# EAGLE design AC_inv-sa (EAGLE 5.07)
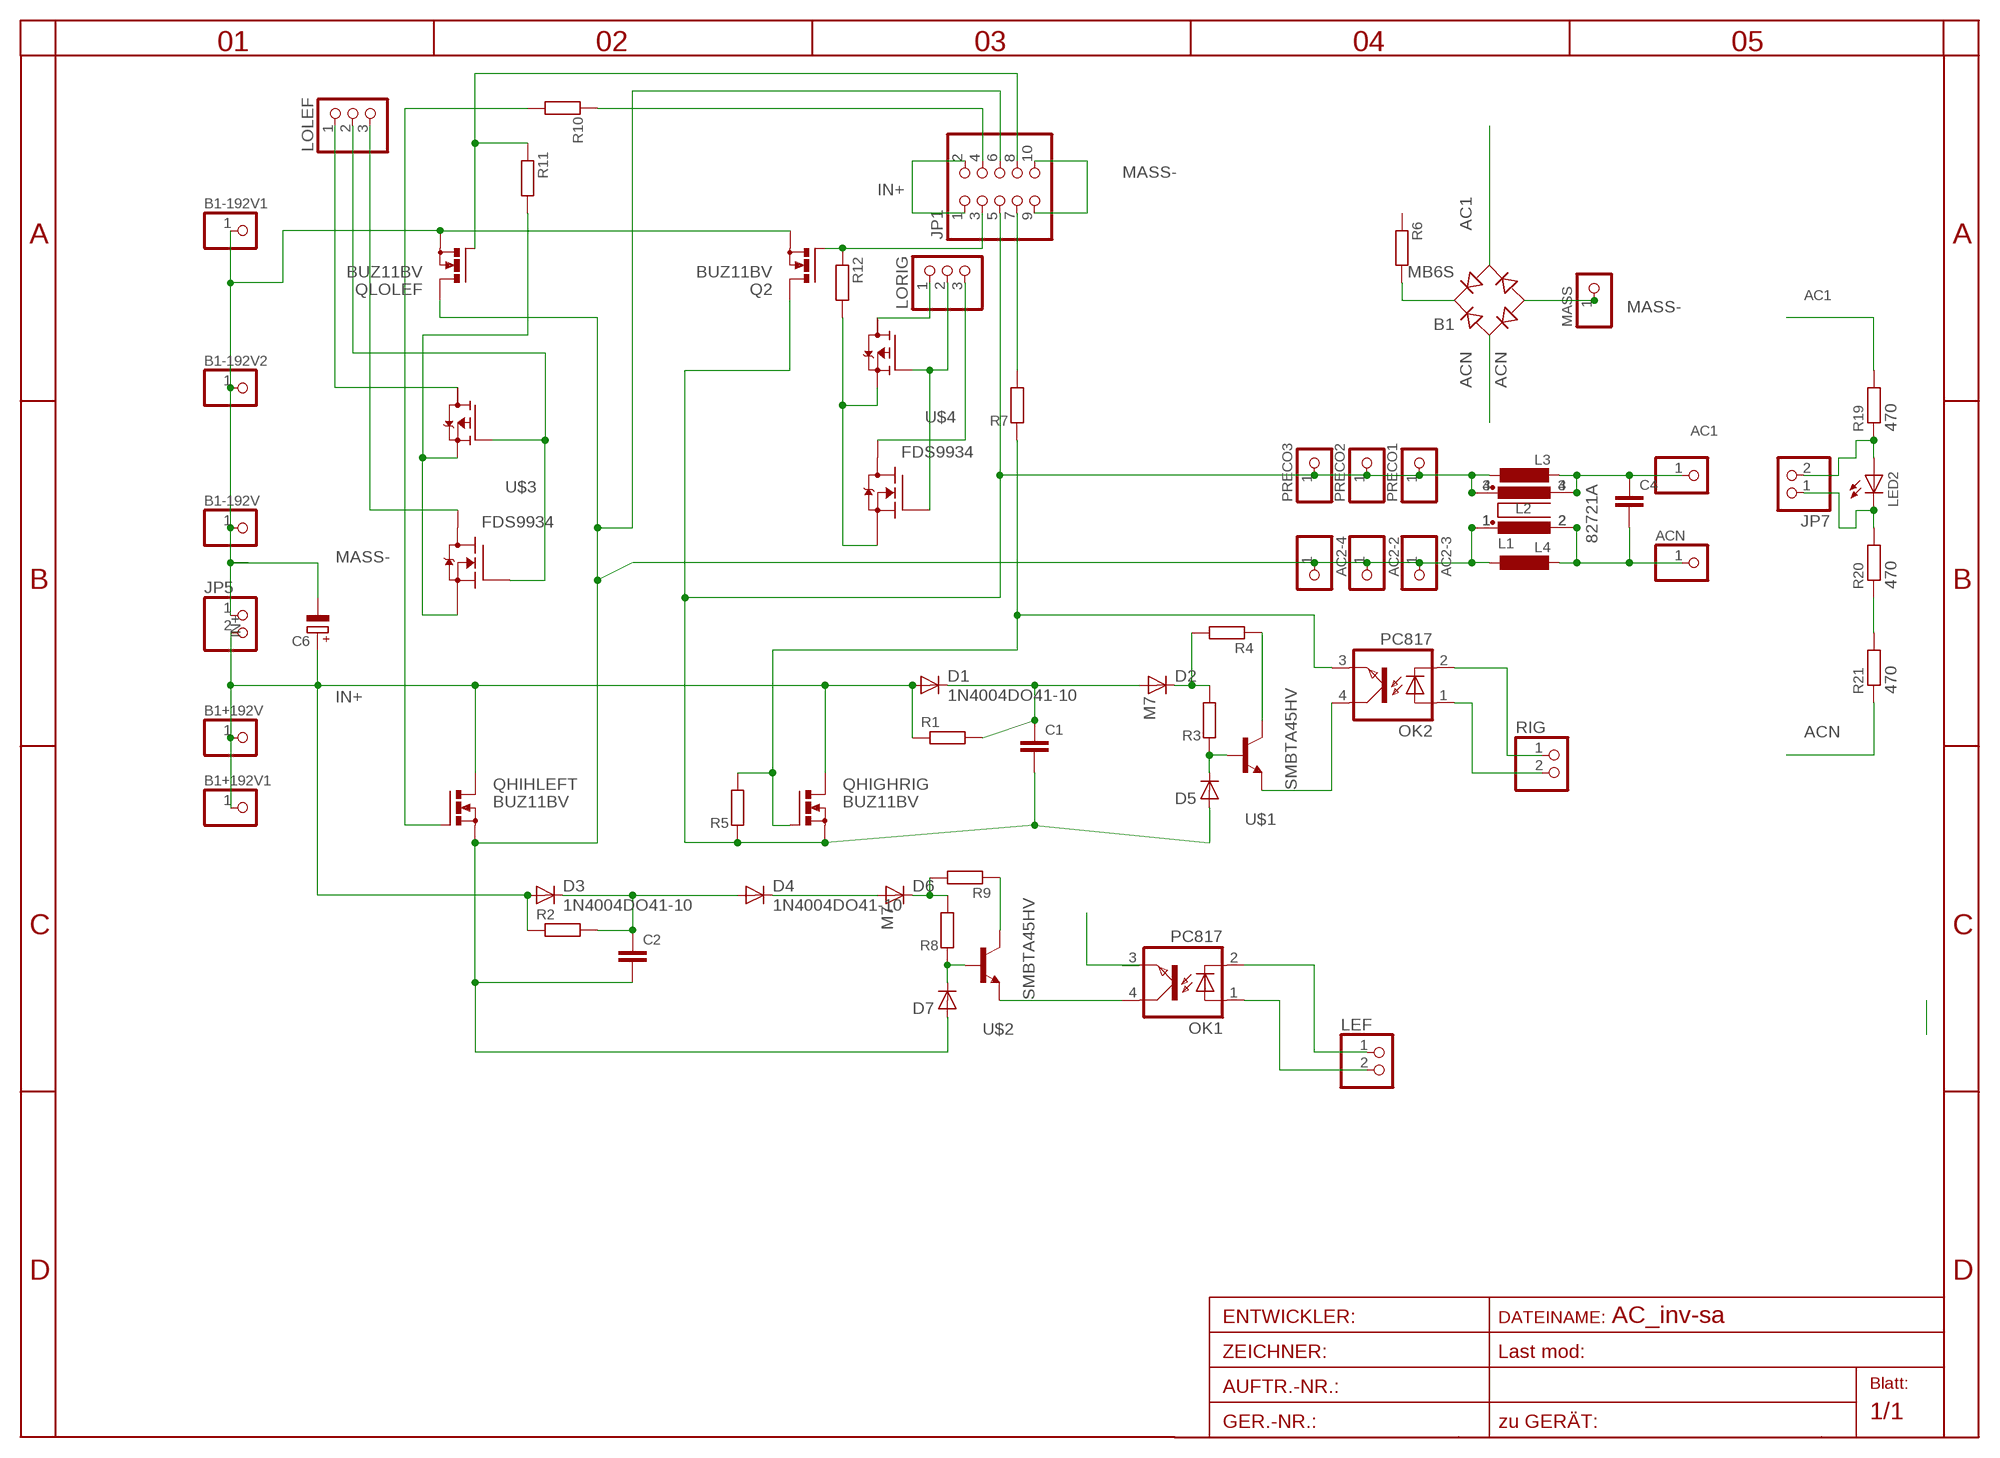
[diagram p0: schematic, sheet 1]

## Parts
AC1  PINHD-1X14.5MM  [1X4MM5]
AC2-2  PINHD-1X13MM2  [1X3MM2]
AC2-3  PINHD-1X13MM2  [1X3MM2]
AC2-4  PINHD-1X12MM3  [1X2MM3]
ACN  PINHD-1X14.5MM  [1X4MM5]
B1  MB6S  [SOIC-4]
B1+192V  PINHD-1X13MM2  [1X3MM2]
B1+192V1  PINHD-1X13MM2  [1X3MM2]
B1-192V  PINHD-1X13MM2  [1X3MM2]
B1-192V1  PINHD-1X13MM2  [1X3MM2]
B1-192V2  PINHD-1X13MM2  [1X3MM2]
C1  C-EU102-043X133  [C102-043X133]
C2  C-EU102-043X133  [C102-043X133]
C4  C-EU102-043X133  [C102-043X133]
C6  CPOL-EUE10-20  [EB20D]
D1  1N4004DO41-10  [DO41-10]
D2  M7  1N4004DO41-10  [DO41-10]
D3  1N4004DO41-10  [DO41-10]
D4  1N4004DO41-10  [DO41-10]
D5  DIODE-MINIMELF  [MINIMELF]
D6  M7  1N4004DO41-10  [DO41-10]
D7  DIODE-MINIMELF  [MINIMELF]
JP1  PINHD-2X5  [2X05]
JP5  PINHD-1X2STR  [1X02]
JP7  PINHD-1X2STR  [1X02]
L1  R1405VB1  [B1]
L2  82721A  [82721A]
L3  L-EU2200-15.24  [2200-15.24]
L4  L-EU2200-15.24  [2200-15.24]
LED2  LED3MM  [LED3MM]
LEF  PINHD-1X2STR  [1X02]
LOLEF  PINHD-1X3  [1X03]
LORIG  PINHD-1X3  [1X03]
MASS  PINHD-1X13MM2  [1X3MM2]
OK1  PC817  [DIL04]
OK2  PC817  [DIL04]
PRECO1  PINHD-1X12MM3  [1X2MM3]
PRECO2  PINHD-1X13MM2  [1X3MM2]
PRECO3  PINHD-1X13MM2  [1X3MM2]
Q2  BUZ11BV  [TO220BV]
QHIGHRIG  BUZ11BV  [TO220BV]
QHIHLEFT  BUZ11BV  [TO220BV]
QLOLEF  BUZ11BV  [TO220BV]
R1  R-EU_0207/10  [0207/10]
R2  R-EU_0207/10  [0207/10]
R3  R-EU_0207/40  [0207/40]
R4  R-EU_0207/50  [0207/50]
R5  R-EU_R1206  [R1206]
R6  R-EU_0207/60  [0207/60]
R7  R-EU_R1206  [R1206]
R8  R-EU_0207/40  [0207/40]
R9  R-EU_0207/50  [0207/50]
R10  R-EU_R1206  [R1206]
R11  R-EU_0207/60  [0207/60]
R12  R-EU_0207/60  [0207/60]
R19  470  R-EU_0204/5  [0204/5]
R20  470  R-EU_0204/2V  [0204V]
R21  470  R-EU_0204/5  [0204/5]
RIG  PINHD-1X2STR  [1X02]
U$1  SMBTA45HV  [SOT23HV]
U$2  SMBTA45HV  [SOT23HV]
U$3  FDS9934  [SO-8]
U$4  FDS9934  [SO-8]

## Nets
AC1: AC1.1 B1.~2(AC2) C4.1 L1.4 L2.3 L3.2 R19.2
ACN: ACN.1 B1.~1(AC1) C4.2 L1.2 L2.2 L4.2 R21.1
BLACK: AC2-2.1 AC2-3.1 AC2-4.1 C2.2 D7.A JP1.6 L1.1 L2.1 L4.1 QHIHLEFT.S QLOLEF.D
IN+: B1+192V1.1 B1+192V.1 C6.+ D1.A D3.A JP1.1 JP1.2 JP5.2 QHIGHRIG.D QHIHLEFT.D R1.1 R2.1
MASS-: B1-192V1.1 B1-192V2.1 B1-192V.1 B1.- C6.- JP1.9 JP1.10 JP5.1 MASS.1 Q2.S QLOLEF.S
N$1: C1.1 D1.C D2.A R1.2
N$2: D2.C R3.2 R4.2
N$3: LEF.1 OK1.2(C)
N$4: QHIHLEFT.G R10.2
N$6: JP7.2 LED2.A R19.1
N$7: OK2.1(A) RIG.2
N$9: JP7.1 LED2.K(C) R20.2
N$11: D4.C D6.A
N$12: C2.1 D3.C D4.A R2.2
N$13: R20.1 R21.2
N$14: R4.1 U$1.3(C)
N$15: OK2.4(COL) U$1.2(E)
N$16: D5.C R3.1 U$1.1(B)
N$17: OK2.2(C) RIG.1
N$20: OK2.3(EMIT) QHIGHRIG.G R5.2 R7.1
N$21: D6.C R8.2 R9.2
N$22: R9.1 U$2.3(C)
N$23: OK1.4(COL) U$2.2(E)
N$24: D7.C R8.1 U$2.1(B)
N$26: LOLEF.3 U$3.7(Q1D2)
N$27: LOLEF.1 U$3.5(Q2D2)
N$29: LOLEF.2 U$3.2(Q1G) U$3.4(Q2G)
N$33: B1.+ R6.2
N$34: R11.2 U$3.1(Q1S) U$3.3(Q2S)
N$35: LORIG.1 U$4.5(Q2D2)
N$36: R12.2 U$4.1(Q1S) U$4.3(Q2S)
N$37: LORIG.3 U$4.7(Q1D2)
N$38: LORIG.2 U$4.2(Q1G) U$4.4(Q2G)
P3: JP1.3 Q2.G R12.1
P4: JP1.4 R10.1
P7: JP1.7 LEF.2 OK1.1(A) R7.2
P8: JP1.8 QLOLEF.G R11.1
RED: C1.2 D5.A JP1.5 L1.3 L2.4 L3.1 PRECO1.1 PRECO2.1 PRECO3.1 Q2.D QHIGHRIG.S R5.1
Unconnected: OK1.3(EMIT) R6.1 U$3.6(Q2D) U$3.8(Q1D1) U$4.6(Q2D) U$4.8(Q1D1)

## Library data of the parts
AC1 AC2-2-AC2-4 ACN B1+192V B1+192V1 B1-192V B1-192V1 B1-192V2 MASS PRECO1-PRECO3 = pinhead:PINHD-1X1: PIN HEADER
B1 = rectifier:MB*S: Bridge Rectifier Source: http://www.fairchildsemi.com/ds/MB/MB6S.pdf
C1 C2 C4 = rcl:C-EU: CAPACITOR, European symbol
C6 = rcl:CPOL-EU: POLARIZED CAPACITOR, European symbol
D1-D4 D6 = diode:1N4004: DIODE
D5 D7 = diode:DIODE-: DIODE
JP1 = pinhead:PINHD-2X5: PIN HEADER
JP5 JP7 LEF RIG = pinhead:PINHD-1X2: PIN HEADER
L1 = inductor-nkl:R1405V: Übertrager (verlustarm) bis typ. 400kHz Power transformer (low loss) up to typ. 400kHz
L2 = inductors:82721A: FILTER
L3 L4 = rcl:L-EU: INDUCTOR, European symbol
LED2 = led:LED: LED
LOLEF LORIG = pinhead:PINHD-1X3: PIN HEADER
OK1 OK2 = optocoupler:PC817: SHARP OPTO COUPLER
Q2 QHIGHRIG QHIHLEFT QLOLEF = transistor-power:BUZ11: N-CHANNEL MOS FET
R1-R12 R19-R21 = rcl-2:R-EU_: RESISTOR, European symbol
U$1 U$2 = transistor-npn:SMBTA45
U$3 U$4 = transistor-fet:FDS9934

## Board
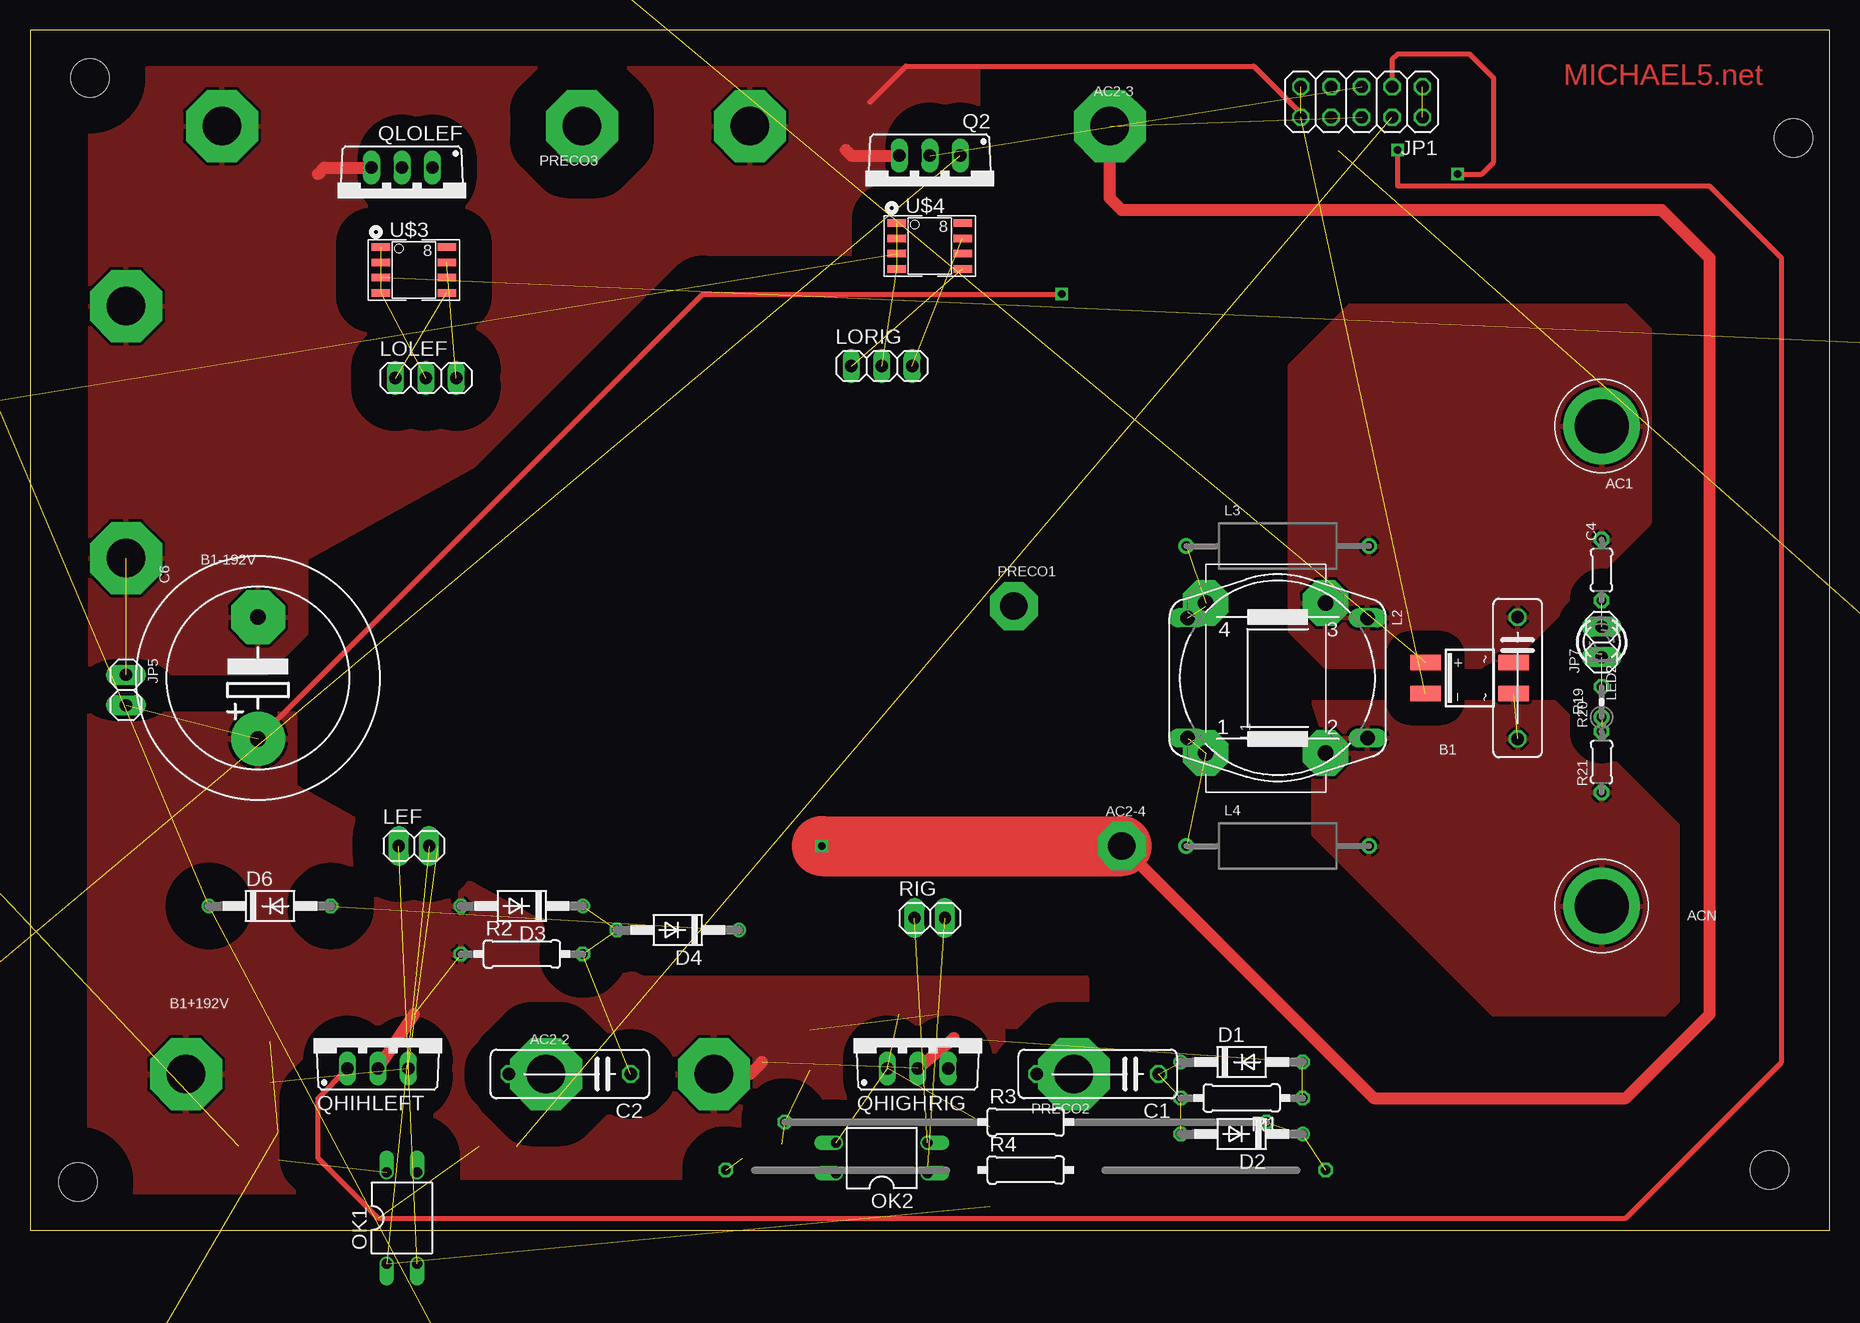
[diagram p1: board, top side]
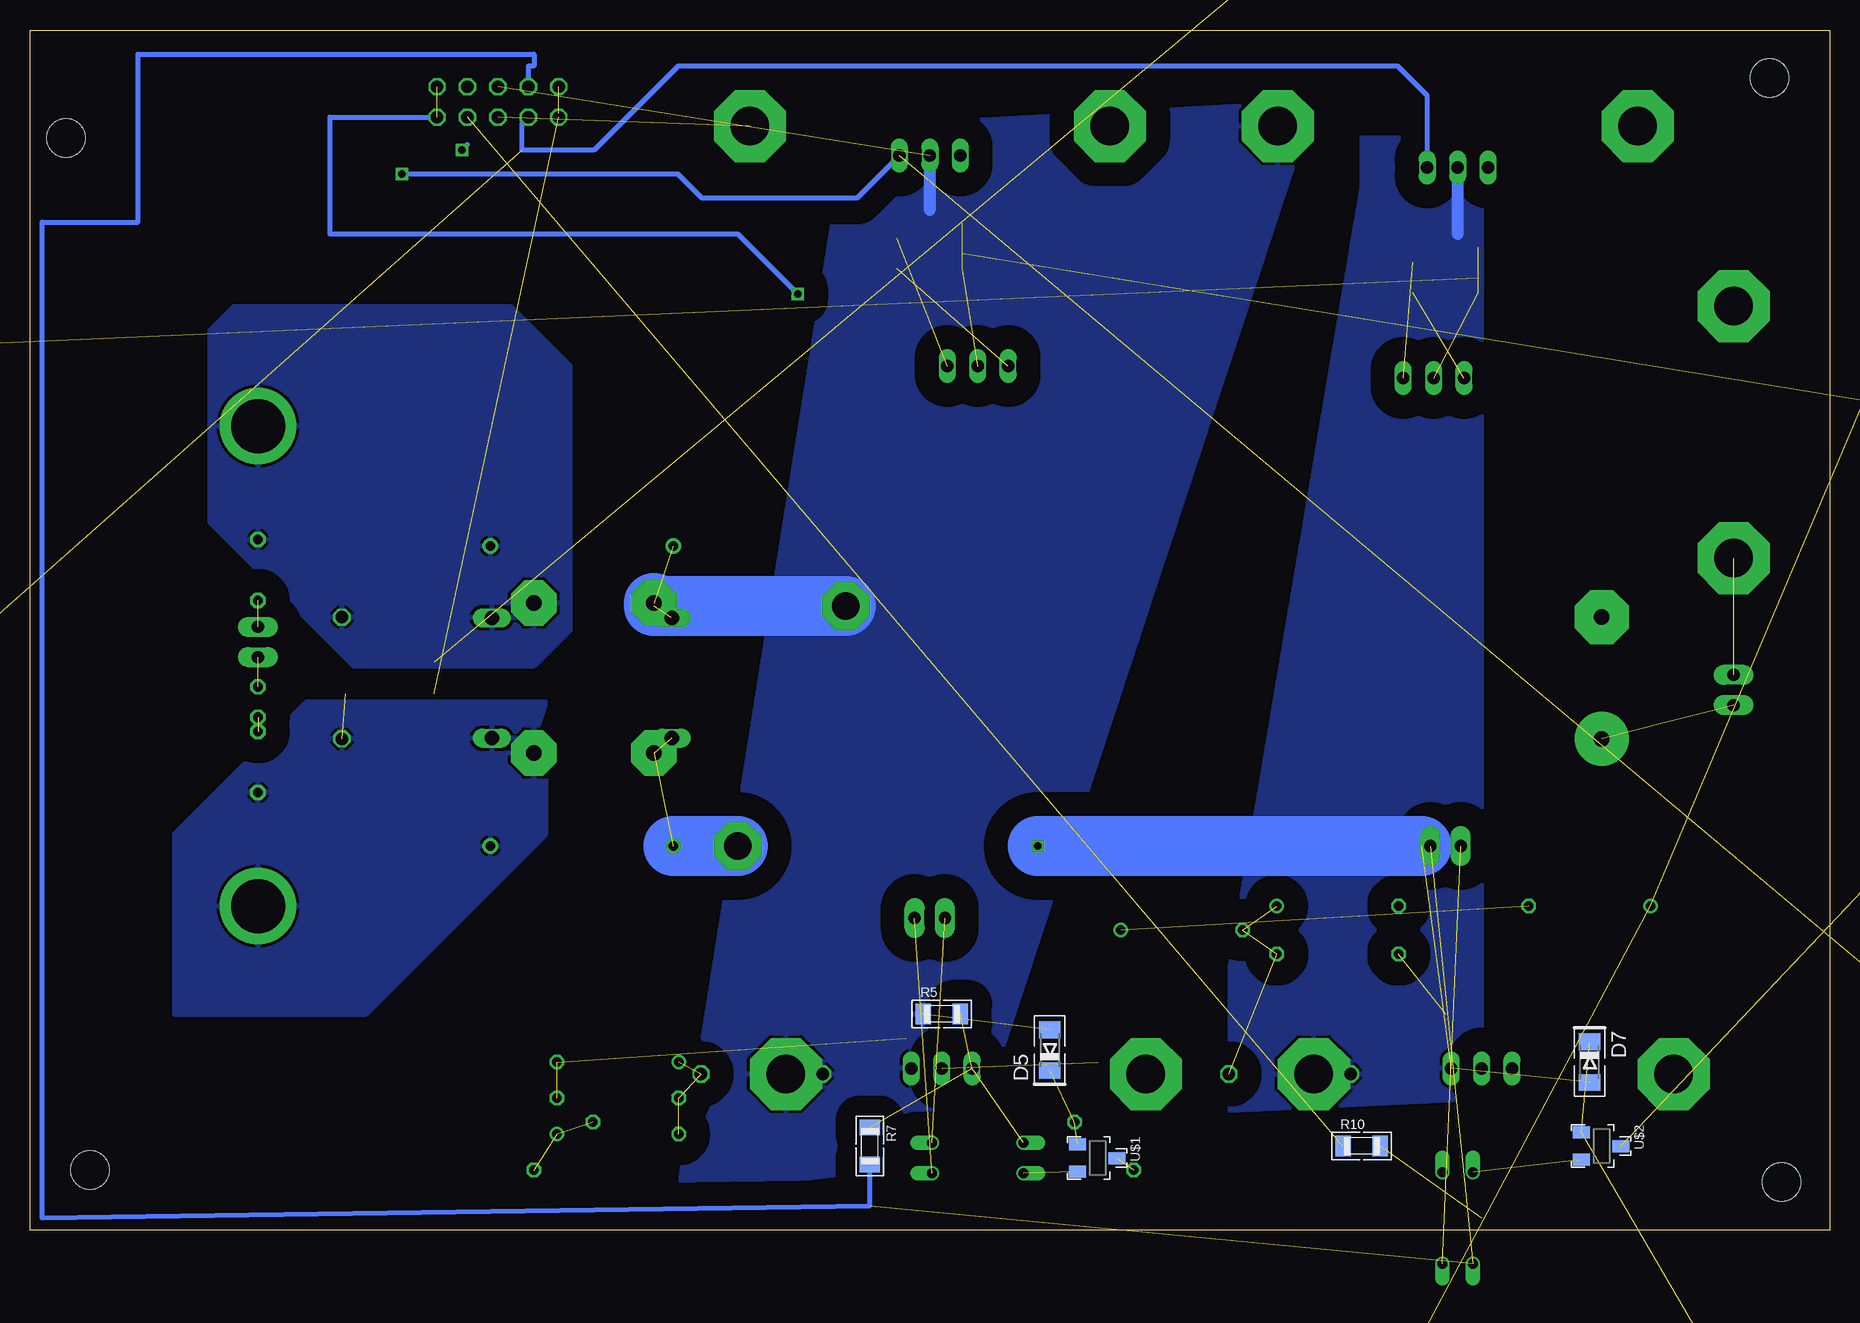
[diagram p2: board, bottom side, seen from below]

Size 150 x 100 mm. Coordinates in mm from the lower left corner, seen from the top.
Outline: 0,0 150,0 150,100 0,100 0,0
Copper layers (1*16): Top 0.035mm / dielectric 1.5mm / Bottom 0.035mm
Design rules "default *": minimum track width 12mil, minimum drill 24mil, track to track 8mil, track to pad 8mil, pad to pad 8mil, via to via 8mil, smd to smd 8mil, copper to edge 40mil, drill to drill 8mil, minimum pad ring 8mil, minimum via ring 8mil, stop-mask expansion 4mil, vias tented up to drill 0mil, thermal gap 10mil
Holes 3.2 mm at 5,96 4,4 147,91 145,5

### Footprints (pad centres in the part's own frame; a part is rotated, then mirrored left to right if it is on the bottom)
1X4MM5 = drill 4.5 pad 6.35 round: 1 0,0
1X3MM2 = drill 3.2 pad 6 octagon: 1 0,0
1X2MM3 = drill 2.3 pad 4 octagon: 1 0,0
SOIC-4 = smd 1.27 x 2.54: + 1.3,3.685; - -1.3,3.685; ~1 -1.3,-3.685; ~2 1.3,-3.685
C102-043X133 = drill 1.016 octagon: 1 -5.08,0; 2 5.08,0
EB20D = drill 1.3 pad 4.5 round: + -5.08,0 | drill 1.3 pad 4.5 octagon: - 5.08,0
DO41-10 = drill 0.8 octagon: A 5.08,0 | drill 0.8 round: C -5.08,0
MINIMELF = smd 1.4 x 1.8: A 1.7,0; C -1.7,0
2X05 = drill 1.016 octagon: 1 -5.08,-1.27; 2 -5.08,1.27; 3 -2.54,-1.27; 4 -2.54,1.27; 5 0,-1.27; 6 0,1.27; 7 2.54,-1.27; 8 2.54,1.27; 9 5.08,-1.27; 10 5.08,1.27
1X02 = drill 1.016 pad 1.676 long: 1 -1.27,0; 2 1.27,0
B1 = drill 1.27 pad 3.81 octagon: 1 -6.25,5; 2 -6.25,-5; 3 6.25,5; 4 6.25,-5
82721A = drill 1.194 long: 1 7.493,5.004; 2 -7.493,5.004; 3 -7.493,-5.004; 4 7.493,-5.004
2200-15.24 = drill 0.8 pad 1.27 round: 1 -7.62,0; 2 7.62,0
LED3MM = drill 0.8 pad 1.27 octagon: A -1.27,0; K 1.27,0
1X03 = drill 1.016 long: 1 -2.54,0; 2 0,0; 3 2.54,0
DIL04 = drill 0.813 offset: 1 -1.27,-3.81; 2 1.27,-3.81; 3 1.27,3.81; 4 -1.27,3.81
TO220BV = drill 1.016 long: D 0,-2.54; G -2.54,-2.54; S 2.54,-2.54
0207/10 = drill 0.813 octagon: 1 -5.08,0; 2 5.08,0
0207/40 = drill 0.813 octagon: 1 -20.08,0; 2 20.08,0
0207/50 = drill 0.813 octagon: 1 -25,0; 2 25,0
R1206 = smd 1.3 x 1.7: 1 -1.55,0; 2 1.55,0
0207/60 = drill 0.813 octagon: 1 -30,0; 2 30,0
0204/5 = drill 0.8 pad 1.27 octagon: 1 -2.54,0; 2 2.54,0
0204V = drill 0.8 pad 1.27 octagon: 1 -1.27,0; 2 1.27,0
SOT23HV = smd 1 x 1.4: 1 -1.15,-1.7; 2 1.15,-1.7; 3 0,1.6
SO-8 = smd 1.524 x 0.61: 1 -2.743,1.905; 2 -2.743,0.635; 3 -2.743,-0.635; 4 -2.743,-1.905; 5 2.743,-1.905; 6 2.743,-0.635; 7 2.743,0.635; 8 2.743,1.905

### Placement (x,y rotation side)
AC1  131,67 180 top
AC2-2  43,13 0 top
AC2-3  90,92 0 top
AC2-4  91,32 0 top
ACN  131,27 180 top
B1  120,46 90 top
B1+192V  13,13 0 top
B1+192V1  57,13 0 top
B1-192V  8,56 180 top
B1-192V1  16,92 180 top
B1-192V2  60,92 0 top
C1  89,13 180 top
C2  45,13 180 top
C4  124,46 270 top
C6  19,46 90 top
D1  101,14 0 top
D2  101,8 180 top
D3  41,27 180 top
D4  54,25 180 top
D5  65,15 90 bottom
D6  20,27 0 top
D7  20,14 270 bottom
JP1  111,94 180 top
JP5  8,45 270 top
JP7  131,49 90 top
L1  103,46 90 top
L2  104,46 180 top
L3  104,57 0 top
L4  104,32 0 top
LED2  131,49 270 top
LEF  32,32 0 top
LOLEF  33,71 0 top
LORIG  71,72 0 top
MASS  8,77 0 top
OK1  31,1 0 top
OK2  71,6 90 top
PRECO1  82,52 0 top
PRECO2  87,13 180 top
PRECO3  46,92 180 top
Q2  75,87 180 top
QHIGHRIG  74,16 0 top
QHIHLEFT  29,16 0 top
QLOLEF  31,86 180 top
R1  101,11 180 top
R2  41,23 0 top
R3  83,9 0 top
R4  83,5 0 top
R5  74,18 0 bottom
R6  not placed on the board
R7  80,7 270 bottom
R8  not placed on the board
R9  not placed on the board
R10  39,7 0 bottom
R11  not placed on the board
R12  not placed on the board
R19  131,55 90 top
R20  131,44 90 top
R21  131,39 90 top
RIG  75,26 0 top
U$1  61,6 270 bottom
U$2  19,7 270 bottom
U$3  32,80 0 top
U$4  75,82 0 top

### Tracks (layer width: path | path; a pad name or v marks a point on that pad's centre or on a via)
AC1
  pour Bottom (isolate 2): 105,72 105,50 108,47 123,47 135,59 135,75 133,77 110,77
  pour Top (isolate 2): 105,72 105,50 108,47 123,47 135,59 135,75 133,77 110,77
ACN  (1 unrouted)
  pour Bottom (isolate 2, rank 2): 107,44 127,44 138,33 138,18 122,18 107,33 107,40 108,41
  pour Top (isolate 2, rank 2): 107,44 127,44 138,33 138,18 122,18 107,33 107,40 108,41
BLACK  (via drill 0.6)  (5 unrouted)
  Top 1: AC2-3.1 90,86 91,85 136,85 140,81 140,18 133,11 112,11 AC2-4.1
  Top 5: v66,32 AC2-4.1
  Bottom 1: 31,83 QLOLEF.D
  Bottom 5: AC2-4.1 L4.1 | 34,32 v66,32
  pour Bottom (isolate 2): 29,91 39,91 39,87 50,22 50,10 29,11
IN+  (via drill 0.6)  (6 unrouted)
  Top 0.406: v86,78 56.08,78 C6.+
  Top 1: QHIGHRIG.D 77,16 | B1+192V1.1 60,13 61,14 | QHIHLEFT.D 32,18
  Bottom 0.406: 116,92.73 JP1.2 125,92.73 125,83 116,83 91,83 v86,78
  pour Top (isolate 3): 5,43 22,43 22,37 51,21 88,21 88,17 81,17 81,3 5,3
MASS-  (3 unrouted)
  Top 0.406: JP1.10 105.92,93.08 102,97 73,97 70,94
  Top 1: QLOLEF.S 24.54,88.54 24,88 | Q2.S 68.46,89.54 68,90
  pour Top (isolate 3, rank 3): 5,46 23,46 23,56 79,87 79,97 10,97 5,92
N$1  (3 unrouted)
N$2  (2 unrouted)
N$3  (1 unrouted)
N$4  (via drill 0.6)  (1 unrouted)
  Top 0.406: v114,90 114,87 140,87 146,81 146,14 133,1 29,1 24,6 24,11 QHIHLEFT.G
  Bottom 0.406: v114,90 113.54,90.46
N$6  (1 unrouted)
N$7  (1 unrouted)
N$9  (1 unrouted)
N$11  (1 unrouted)
N$12  (3 unrouted)
N$13  (1 unrouted)
N$14  (1 unrouted)
N$15  (1 unrouted)
N$16  (2 unrouted)
N$17  (1 unrouted)
N$20  (3 unrouted)
N$21  (2 unrouted)
N$22  (1 unrouted)
N$23  (1 unrouted)
N$24  (2 unrouted)
N$26  (1 unrouted)
N$27  (1 unrouted)
N$29  (2 unrouted)
N$33  (1 unrouted)
N$34  (2 unrouted)
N$35  (1 unrouted)
N$36  (2 unrouted)
N$37  (1 unrouted)
N$38  (2 unrouted)
P3  (via drill 0.6)  (1 unrouted)
  Top 0.406: JP1.3 113.54,97.54 114,98 120,98 122,96 122,89 121,88 v119,88
  Bottom 0.406: v119,88 96,88 94,86 81.08,86 Q2.G
P4  (1 unrouted)
P7  (2 unrouted)
  Bottom 0.406: R7.2 80,2 149,1 149,84 141,84 141,98 108,98 108,97 108.46,97 JP1.7
P8  (1 unrouted)
  Bottom 0.406: QLOLEF.G 33.54,94.54 36,97 96,97 103,90 109,90 109,92.19 JP1.8
RED  (4 unrouted)
  Bottom 1: 75,85 Q2.D
  Bottom 5: PRECO1.1 98,52 L1.3
  pour Bottom (isolate 2): 43,94 80,92 80,91 82,91 96,3 72,6

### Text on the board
Top: MICHAEL5.net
